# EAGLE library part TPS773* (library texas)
250-mA LDO REGULATORS WITH RESET OUTPUT WITH 8-PIN MSOP PACKAGING Source: http://focus.ti.com/lit/ds/symlink/tps77333.pdf
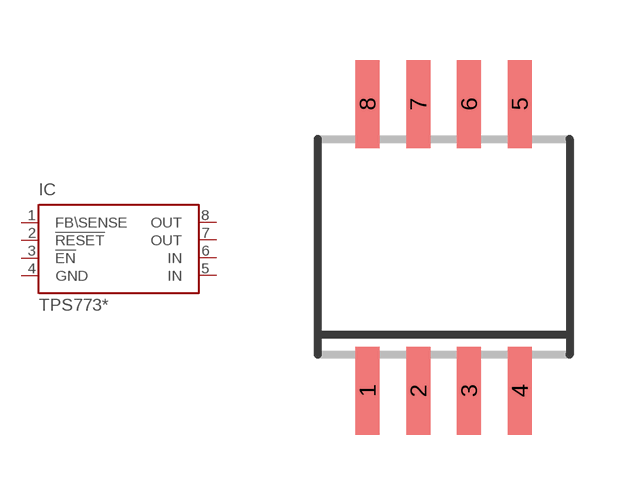
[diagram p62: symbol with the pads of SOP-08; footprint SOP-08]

Designator prefix IC

## TPS77301 (MF: TEXAS INSTRUMENT CONNECTORS; MPN: TPS77301DGK; OC_FARNELL: 1510194; OC_NEWARK: 77C1213), TPS77315 (MF: TEXAS INSTRUMENT CONNECTORS; MPN: TPS77315DGK; OC_FARNELL: 1412890; OC_NEWARK: 77C1215), TPS77316 (MF: TEXAS INSTRUMENT CONNECTORS; MPN: TPS77316DGK; OC_FARNELL: 1412891; OC_NEWARK: 77C1217), TPS77318 (MF: TEXAS INSTRUMENT CONNECTORS; MPN: TPS77318DGK; OC_FARNELL: 1412893; OC_NEWARK: 77C1219), TPS77327 (MF: TEXAS INSTRUMENT CONNECTORS; MPN: TPS77327DGK; OC_FARNELL: unknown; OC_NEWARK: 77C1221), TPS77328 (MF: TEXAS INSTRUMENT CONNECTORS; MPN: TPS77328DGK; OC_FARNELL: unknown; OC_NEWARK: 77C1223), TPS77333 (MF: TEXAS INSTRUMENTS; MPN: TPS77333DGK; OC_FARNELL: 1510195; OC_NEWARK: 02M1919), TPS77350 (MF: TEXAS INSTRUMENT CONNECTORS; MPN: TPS77350DGK; OC_FARNELL: 1412894; OC_NEWARK: 77C1226)  [SOP-08]
1  FB\SENSE  in
2  !RESET  in
3  !EN  in
4  GND  pwr
5  IN  in
6  IN  in
7  OUT  out
8  OUT  pas

## Footprint SOP-08 (pad centres in mm)
PS (R-PDSO-G8) Source: http://focus.ti.com .. sn65176b.pdf
smd 0.6 x 2.2: 1 -1.905,-3.6; 2 -0.635,-3.6; 3 0.635,-3.6; 4 1.905,-3.6; 5 1.905,3.575; 6 0.635,3.575; 7 -0.635,3.575; 8 -1.905,3.575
